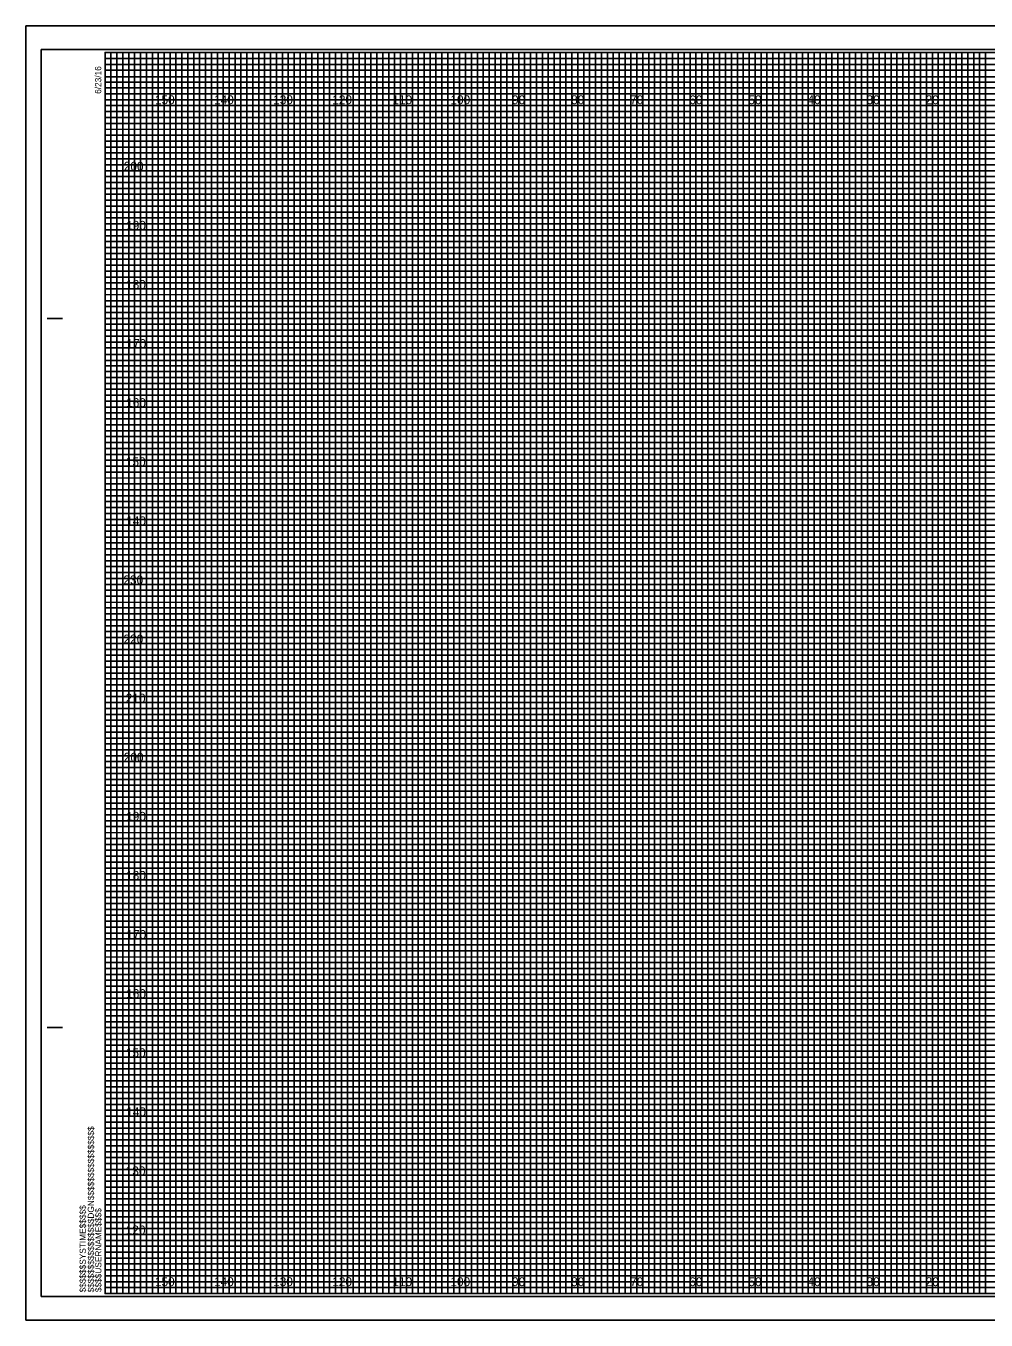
# Model space of a CAD drawing. Extents: x -13 to 323, y -5 to 1754.
# Drawn here: x -13.4 to 149.1, y 1315.5 to 1534.5 of the extents above; entities that cross this region are included whole.
import ezdxf

# ---------------------------------------------------------------- set-up
doc = ezdxf.new("R2010")
doc.units = 0
for name, color, linetype in [('Exist Cross Section Cell', 7, 'Continuous'), ('Exist XS Center Line Elevation Label', 7, 'Continuous'), ('Exist XS Ground Line', 7, 'Continuous'), ('Prop CMT Pvmt Course 1', 7, 'Continuous'), ('Prop CMT Pvmt Course 2', 7, 'Continuous'), ('Prop CMT Pvmt Course 3', 7, 'Continuous'), ('Prop CMT Shld Paved Course 1', 7, 'Continuous'), ('Prop CMT Shld Paved Course 2', 7, 'Continuous'), ('Prop CMT Subgrade Earthwork', 7, 'Continuous'), ('Prop XS Ditch Standard Text', 7, 'Continuous'), ('Scratch_Level_0', 7, 'Continuous')]:
    doc.layers.add(name, color=color, linetype=linetype)

msp = doc.modelspace()

# ---------------------------------------------------------------- linework, layer by layer
at = {"layer": 'Exist XS Center Line Elevation Label'}
for points in [[(0, 1530), (5, 1530), (5, 1320), (15, 1320), (15, 1530), (25, 1530), (25, 1320), (35, 1320), (35, 1530), (45, 1530), (45, 1320), (55, 1320), (55, 1530), (65, 1530), (65, 1320), (75, 1320), (75, 1530), (85, 1530), (85, 1320), (95, 1320), (95, 1530), (105, 1530), (105, 1320), (115, 1320), (115, 1530), (125, 1530), (125, 1320), (135, 1320), (135, 1530), (145, 1530), (145, 1320), (155, 1320)], [(0, 1525), (275, 1525)], [(0, 1505), (320, 1505), (320, 1515), (0, 1515)], [(0, 1485), (320, 1485), (320, 1495), (0, 1495)], [(0, 1465), (320, 1465), (320, 1475), (0, 1475)], [(0, 1445), (320, 1445), (320, 1455), (0, 1455)], [(0, 1425), (320, 1425), (320, 1435), (0, 1435)], [(0, 1405), (320, 1405), (320, 1415), (0, 1415)], [(0, 1385), (320, 1385), (320, 1395), (0, 1395)], [(0, 1365), (320, 1365), (320, 1375), (0, 1375)], [(0, 1345), (320, 1345), (320, 1355), (0, 1355)], [(0, 1325), (320, 1325), (320, 1335), (0, 1335)]]:
    msp.add_lwpolyline(points, dxfattribs=at)
at = {"layer": 'Exist XS Ground Line'}
for p, q in [((10, 1530), (0, 1530)), ((10, 1320), (10, 1530)), ((30, 1530), (20, 1530)), ((20, 1530), (20, 1320)), ((30, 1320), (30, 1530)), ((50, 1530), (40, 1530)), ((40, 1530), (40, 1320)), ((50, 1320), (50, 1530)), ((70, 1530), (60, 1530)), ((60, 1530), (60, 1320)), ((70, 1320), (70, 1530)), ((90, 1530), (80, 1530)), ((80, 1530), (80, 1320)), ((90, 1320), (90, 1530)), ((110, 1530), (100, 1530)), ((100, 1530), (100, 1320)), ((110, 1320), (110, 1530)), ((130, 1530), (120, 1530)), ((120, 1530), (120, 1320)), ((130, 1320), (130, 1530)), ((150, 1530), (140, 1530)), ((140, 1530), (140, 1320)), ((20, 1320), (10, 1320)), ((40, 1320), (30, 1320)), ((60, 1320), (50, 1320)), ((80, 1320), (70, 1320)), ((100, 1320), (90, 1320)), ((120, 1320), (110, 1320)), ((140, 1320), (130, 1320))]:
    msp.add_line(p, q, dxfattribs=at)
for points in [[(0, 1520), (320, 1520), (320, 1510), (0, 1510)], [(0, 1500), (320, 1500), (320, 1490), (0, 1490)], [(0, 1480), (320, 1480), (320, 1470), (0, 1470)], [(0, 1460), (320, 1460), (320, 1450), (0, 1450)], [(0, 1440), (320, 1440), (320, 1430), (0, 1430)], [(0, 1420), (320, 1420), (320, 1410), (0, 1410)], [(0, 1400), (320, 1400), (320, 1390), (0, 1390)], [(0, 1380), (320, 1380), (320, 1370), (0, 1370)], [(0, 1360), (320, 1360), (320, 1350), (0, 1350)], [(0, 1340), (320, 1340), (320, 1330), (0, 1330)]]:
    msp.add_lwpolyline(points, dxfattribs=at)
at = {"layer": 'Prop CMT Pvmt Course 1'}
for p, q in [((323.3, 1534.5), (-13.4, 1534.5)), ((-13.4, 1534.5), (-13.4, 1315.5)), ((-13.4, 1315.5), (323.3, 1315.5))]:
    msp.add_line(p, q, dxfattribs=at)
at = {"layer": 'Prop CMT Pvmt Course 2'}
msp.add_lwpolyline([(-13.4, 1315.5), (323.3, 1315.5), (323.3, 1534.5), (-13.4, 1534.5)], close=True, dxfattribs=at)
at = {"layer": 'Prop CMT Pvmt Course 3'}
msp.add_lwpolyline([(-10.8, 1319.5), (322.4, 1319.5), (322.4, 1530.5), (-10.8, 1530.5)], close=True, dxfattribs=at)
at = {"layer": 'Prop CMT Shld Paved Course 1'}
for p, q in [((-9.8, 1485), (-7.3, 1485)), ((-9.7, 1485), (-7.2, 1485)), ((-9.8, 1365), (-7.3, 1365)), ((-9.7, 1365), (-7.2, 1365)), ((0, 1320), (0, 1320)), ((0, 1320), (0, 1320)), ((0, 1320), (0, 1320)), ((0, 1320), (0, 1320)), ((0, 1320), (0, 1320)), ((0, 1320), (0, 1320)), ((0, 1320), (0, 1320))]:
    msp.add_line(p, q, dxfattribs=at)
msp.add_lwpolyline([(320, 1530), (0, 1530), (0, 1320), (320, 1320)], close=True, dxfattribs=at)
at = {"layer": 'Prop CMT Shld Paved Course 2'}
for points in [[(0, 1320), (1, 1320), (1, 1530), (2, 1530), (2, 1320)], [(2, 1320), (3, 1320), (3, 1530), (4, 1530), (4, 1320)], [(5, 1320), (6, 1320), (6, 1530), (7, 1530), (7, 1320)], [(7, 1320), (8, 1320), (8, 1530), (9, 1530), (9, 1320)], [(10, 1320), (11, 1320), (11, 1530), (12, 1530), (12, 1320)], [(12, 1320), (13, 1320), (13, 1530), (14, 1530), (14, 1320)], [(15, 1320), (16, 1320), (16, 1530), (17, 1530), (17, 1320)], [(17, 1320), (18, 1320), (18, 1530), (19, 1530), (19, 1320)], [(20, 1320), (21, 1320), (21, 1530), (22, 1530), (22, 1320)], [(22, 1320), (23, 1320), (23, 1530), (24, 1530), (24, 1320)], [(25, 1320), (26, 1320), (26, 1530), (27, 1530), (27, 1320)], [(27, 1320), (28, 1320), (28, 1530), (29, 1530), (29, 1320)], [(30, 1320), (31, 1320), (31, 1530), (32, 1530), (32, 1320)], [(32, 1320), (33, 1320), (33, 1530), (34, 1530), (34, 1320)], [(35, 1320), (36, 1320), (36, 1530), (37, 1530), (37, 1320)], [(37, 1320), (38, 1320), (38, 1530), (39, 1530), (39, 1320)], [(40, 1320), (41, 1320), (41, 1530), (42, 1530), (42, 1320)], [(42, 1320), (43, 1320), (43, 1530), (44, 1530), (44, 1320)], [(45, 1320), (46, 1320), (46, 1530), (47, 1530), (47, 1320)], [(47, 1320), (48, 1320), (48, 1530), (49, 1530), (49, 1320)], [(50, 1320), (51, 1320), (51, 1530), (52, 1530), (52, 1320)], [(52, 1320), (53, 1320), (53, 1530), (54, 1530), (54, 1320)], [(55, 1320), (56, 1320), (56, 1530), (57, 1530), (57, 1320)], [(57, 1320), (58, 1320), (58, 1530), (59, 1530), (59, 1320)], [(60, 1320), (61, 1320), (61, 1530), (62, 1530), (62, 1320)], [(62, 1320), (63, 1320), (63, 1530), (64, 1530), (64, 1320)], [(65, 1320), (66, 1320), (66, 1530), (67, 1530), (67, 1320)], [(67, 1320), (68, 1320), (68, 1530), (69, 1530), (69, 1320)], [(70, 1320), (71, 1320), (71, 1530), (72, 1530), (72, 1320)], [(72, 1320), (73, 1320), (73, 1530), (74, 1530), (74, 1320)], [(75, 1320), (76, 1320), (76, 1530), (77, 1530), (77, 1320)], [(77, 1320), (78, 1320), (78, 1530), (79, 1530), (79, 1320)], [(80, 1320), (81, 1320), (81, 1530), (82, 1530), (82, 1320)], [(82, 1320), (83, 1320), (83, 1530), (84, 1530), (84, 1320)], [(85, 1320), (86, 1320), (86, 1530), (87, 1530), (87, 1320)], [(87, 1320), (88, 1320), (88, 1530), (89, 1530), (89, 1320)], [(90, 1320), (91, 1320), (91, 1530), (92, 1530), (92, 1320)], [(92, 1320), (93, 1320), (93, 1530), (94, 1530), (94, 1320)], [(95, 1320), (96, 1320), (96, 1530), (97, 1530), (97, 1320)], [(97, 1320), (98, 1320), (98, 1530), (99, 1530), (99, 1320)], [(100, 1320), (101, 1320), (101, 1530), (102, 1530), (102, 1320)], [(102, 1320), (103, 1320), (103, 1530), (104, 1530), (104, 1320)], [(105, 1320), (106, 1320), (106, 1530), (107, 1530), (107, 1320)], [(107, 1320), (108, 1320), (108, 1530), (109, 1530), (109, 1320)], [(110, 1320), (111, 1320), (111, 1530), (112, 1530), (112, 1320)], [(112, 1320), (113, 1320), (113, 1530), (114, 1530), (114, 1320)], [(115, 1320), (116, 1320), (116, 1530), (117, 1530), (117, 1320)], [(117, 1320), (118, 1320), (118, 1530), (119, 1530), (119, 1320)], [(120, 1320), (121, 1320), (121, 1530), (122, 1530), (122, 1320)], [(122, 1320), (123, 1320), (123, 1530), (124, 1530), (124, 1320)], [(125, 1320), (126, 1320), (126, 1530), (127, 1530), (127, 1320)], [(127, 1320), (128, 1320), (128, 1530), (129, 1530), (129, 1320)], [(130, 1320), (131, 1320), (131, 1530), (132, 1530), (132, 1320)], [(132, 1320), (133, 1320), (133, 1530), (134, 1530), (134, 1320)], [(135, 1320), (136, 1320), (136, 1530), (137, 1530), (137, 1320)], [(137, 1320), (138, 1320), (138, 1530), (139, 1530), (139, 1320)], [(140, 1320), (141, 1320), (141, 1530), (142, 1530), (142, 1320)], [(142, 1320), (143, 1320), (143, 1530), (144, 1530), (144, 1320)], [(145, 1320), (146, 1320), (146, 1530), (147, 1530), (147, 1320)], [(147, 1320), (148, 1320), (148, 1530), (149, 1530), (149, 1320)]]:
    msp.add_lwpolyline(points, dxfattribs=at)
at = {"layer": 'Prop CMT Subgrade Earthwork'}
for p, q in [((10, 1320), (10, 1530)), ((20, 1320), (20, 1530)), ((30, 1320), (30, 1530)), ((40, 1320), (40, 1530)), ((50, 1320), (50, 1530)), ((60, 1320), (60, 1530)), ((70, 1320), (70, 1530)), ((80, 1320), (80, 1530)), ((90, 1320), (90, 1530)), ((100, 1320), (100, 1530)), ((110, 1320), (110, 1530)), ((120, 1320), (120, 1530)), ((130, 1320), (130, 1530)), ((140, 1320), (140, 1530)), ((0, 1520), (320, 1520)), ((0, 1510), (320, 1510)), ((0, 1500), (320, 1500)), ((0, 1490), (320, 1490)), ((0, 1480), (320, 1480)), ((0, 1470), (320, 1470)), ((0, 1460), (320, 1460)), ((0, 1450), (320, 1450)), ((0, 1440), (320, 1440)), ((0, 1430), (320, 1430)), ((0, 1420), (320, 1420)), ((0, 1410), (320, 1410)), ((0, 1400), (320, 1400)), ((0, 1390), (320, 1390)), ((0, 1380), (320, 1380)), ((0, 1370), (320, 1370)), ((0, 1360), (320, 1360)), ((0, 1350), (320, 1350)), ((0, 1340), (320, 1340)), ((0, 1330), (320, 1330))]:
    msp.add_line(p, q, dxfattribs=at)
at = {"layer": 'Scratch_Level_0'}
for p, q in [((0, 1529), (260, 1529)), ((260, 1527.98), (0, 1527.98)), ((0, 1527.98), (0, 1527)), ((0, 1527), (260, 1527)), ((260, 1525.89), (0, 1525.89)), ((0, 1525.89), (0, 1524)), ((0, 1524), (320, 1524))]:
    msp.add_line(p, q, dxfattribs=at)
for points in [[(0, 1523), (270, 1523), (320, 1523), (320, 1522), (0, 1522)], [(0, 1521), (320, 1521), (320, 1519), (0, 1519)], [(0, 1518), (320, 1518), (320, 1517), (0, 1516.98)], [(0, 1516), (320, 1516), (320, 1514), (0, 1514)], [(0, 1513), (320, 1513), (320, 1512), (0, 1512)], [(0, 1511), (320, 1511), (320, 1509), (0, 1509)], [(0, 1508), (320, 1508), (320, 1507), (0, 1507)], [(0, 1506), (320, 1506), (320, 1504), (0, 1504)], [(0, 1503), (320, 1503), (320, 1502), (0, 1502)], [(0, 1501), (320, 1501), (320, 1499), (0, 1499)], [(0, 1498), (320, 1498), (320, 1497), (0, 1497)], [(0, 1496), (320, 1496), (320, 1493.95), (320, 1493), (320, 1492), (0, 1492)], [(0, 1494), (320, 1494), (320, 1493), (0, 1493)], [(0, 1491), (320, 1491), (320, 1489), (0, 1489.03)], [(0, 1489.03), (320, 1489), (320, 1488), (0, 1488)], [(0, 1487), (320, 1487), (320, 1486), (0, 1486)], [(0, 1484), (320, 1484), (320, 1483), (0, 1483)], [(0, 1482), (320, 1482), (320, 1481), (0, 1481)], [(-0.07, 1478.89), (320, 1478.89), (320, 1477.88), (-0.07, 1477.88)], [(0, 1477), (320, 1477), (320, 1476), (0, 1476)], [(0, 1474), (320, 1474), (320, 1473), (0, 1473)], [(0, 1472), (320, 1472), (320, 1471), (0, 1471)], [(0, 1469), (320, 1469), (320, 1468), (0, 1468)], [(0, 1467), (320, 1467), (320, 1466), (0, 1466)], [(0, 1464), (320, 1464), (320, 1463), (0, 1463)], [(0, 1462), (320, 1462), (320, 1461), (0, 1461)], [(0, 1459), (320, 1459), (319.99, 1457.98), (0, 1458)], [(0, 1457), (320, 1457), (320, 1456), (0, 1456)], [(0, 1454), (320, 1454), (320, 1453), (0, 1453)], [(0, 1452), (320, 1452), (320, 1451), (0, 1451)], [(0, 1449), (320, 1449), (320, 1448), (0, 1448)], [(0, 1447), (320, 1447), (320, 1446), (0, 1446)], [(0, 1444), (320, 1444), (320, 1443), (0, 1443)], [(0, 1442), (320, 1442), (320, 1441), (0, 1441)], [(0, 1439), (320, 1439), (320, 1438), (0, 1438)], [(0, 1436.99), (320.07, 1436.91), (320, 1436), (0, 1436)], [(0, 1434), (320, 1434), (320, 1433), (0, 1433)], [(0, 1432), (320, 1432), (320, 1431), (0, 1431)], [(0, 1429), (320, 1429), (320, 1428), (0, 1428)], [(0, 1427), (320, 1427), (320, 1426), (0, 1426)], [(0, 1424), (320, 1424), (320, 1423), (0, 1423)], [(0, 1422), (320, 1422), (320, 1421), (0, 1421)], [(0, 1419), (320, 1419), (320, 1418), (0, 1418)], [(0, 1417), (320, 1417), (320, 1416), (0, 1416)], [(0, 1414), (320, 1414), (320, 1413), (0, 1413)], [(0, 1412), (320, 1412), (320, 1411), (0, 1411)], [(0, 1409), (320, 1409), (320, 1408), (0, 1408)], [(0, 1407), (320, 1407), (320, 1406), (0, 1406)], [(0, 1404), (320, 1404), (320, 1403), (0, 1403)], [(0, 1402), (320, 1402), (320, 1401), (0, 1401)], [(0, 1399), (320, 1399), (319.99, 1397.98), (0, 1398)], [(0, 1397), (320, 1397), (320, 1396), (0, 1396)], [(0, 1394), (320, 1394), (320, 1393), (0, 1393)], [(0, 1392), (320, 1392), (320, 1391), (0, 1391)], [(0, 1389), (320, 1389), (320, 1388), (0, 1388)], [(0, 1387), (320, 1387), (320, 1386), (0, 1386)], [(0, 1384), (320, 1384), (320, 1383), (0, 1383)], [(0, 1382), (320, 1382), (320, 1381), (0, 1381)], [(0, 1379), (320, 1379), (320, 1378), (0, 1378)], [(0, 1376.99), (320.07, 1376.91), (320, 1376), (0, 1376)], [(0, 1374), (320, 1374), (320, 1373), (0, 1373)], [(0, 1372), (320, 1372), (320, 1371), (0, 1371)], [(0, 1369), (320, 1369), (320, 1368), (0, 1368)], [(0, 1367), (320, 1367), (320, 1366), (0, 1366)], [(0, 1364), (320, 1364), (320, 1363), (0, 1363)], [(0, 1362), (320, 1362), (320, 1361), (0, 1361)], [(0, 1359), (320, 1359), (320, 1358), (0, 1358)], [(0, 1357), (320, 1357), (320, 1356), (0, 1356)], [(0, 1354), (320, 1354), (320, 1353), (0, 1353)], [(0, 1352), (320, 1352), (320, 1351), (0, 1351)], [(0, 1349), (320, 1349), (320, 1348), (0, 1348)], [(0, 1347), (320, 1347), (320, 1346), (0, 1346)], [(0, 1344), (320, 1344), (320, 1343), (0, 1343)], [(0, 1342), (320, 1342), (320, 1341), (0, 1341)], [(0, 1339), (320, 1339), (320, 1338), (0, 1338)], [(0, 1337), (320, 1337), (320, 1336), (0, 1336)], [(0, 1334), (320, 1334), (320, 1333), (0, 1333)], [(0, 1332), (320, 1332), (320, 1331), (0, 1331)], [(0, 1329), (320, 1329), (320, 1328), (0, 1328)], [(0, 1327), (320, 1327), (320, 1326), (0, 1326)], [(0, 1324), (320, 1324), (320, 1323), (0, 1323)], [(0, 1322), (320, 1322), (320, 1321), (0, 1321)]]:
    msp.add_lwpolyline(points, dxfattribs=at)

# ---------------------------------------------------------------- texts
at = {"layer": 'Exist Cross Section Cell'}
for s, p in [('200', (3.17, 1510)), ('190', (3.57, 1500)), ('180', (3.55, 1490)), ('170', (3.61, 1480)), ('160', (3.57, 1470)), ('150', (3.52, 1460)), ('140', (3.57, 1450)), ('230', (3.11, 1440)), ('220', (3.12, 1430)), ('210', (3.5, 1420)), ('200', (3.17, 1410)), ('190', (3.57, 1400)), ('180', (3.55, 1390)), ('170', (3.61, 1380)), ('160', (3.57, 1370)), ('150', (3.52, 1360)), ('140', (3.57, 1350)), ('130', (3.49, 1340)), ('120', (3.5, 1330))]:
    msp.add_text(s, height=1.5, dxfattribs=at).set_placement(p)
at = {"layer": 'Prop CMT Shld Paved Course 1'}
for s, p in [('6/23/16', (-0.65, 1523)), ('$$$$$$$$$$$$$$$$DGN$$$$$$$$$$$$$$$$', (-1.88, 1320.18)), ('$$$$$$SYSTIME$$$$$', (-3.26, 1320.18)), ('$$$$USERNAME$$$$', (-0.62, 1320.23))]:
    msp.add_text(s, height=1.05, rotation=90, dxfattribs=at).set_placement(p)
at = {"layer": 'Prop XS Ditch Standard Text'}
for s, p in [('150', (8.44, 1521.25)), ('140', (18.44, 1521.25)), ('130', (28.44, 1521.25)), ('120', (38.44, 1521.25)), ('110', (48.62, 1521.25)), ('100', (58.44, 1521.25)), ('90', (68.86, 1521.25)), ('80', (78.86, 1521.25)), ('70', (88.86, 1521.25)), ('60', (98.86, 1521.25)), ('50', (108.86, 1521.25)), ('40', (118.86, 1521.25)), ('30', (128.86, 1521.25)), ('20', (138.86, 1521.25)), ('150', (8.44, 1321.25)), ('140', (18.44, 1321.25)), ('130', (28.44, 1321.25)), ('120', (38.44, 1321.25)), ('110', (48.62, 1321.25)), ('100', (58.44, 1321.25)), ('90', (68.86, 1321.25)), ('80', (78.86, 1321.25)), ('70', (88.86, 1321.25)), ('60', (98.86, 1321.25)), ('50', (108.86, 1321.25)), ('40', (118.86, 1321.25)), ('30', (128.86, 1321.25)), ('20', (138.86, 1321.25))]:
    msp.add_text(s, height=1.5, dxfattribs=at).set_placement(p)

doc.saveas('drawing.dxf')
